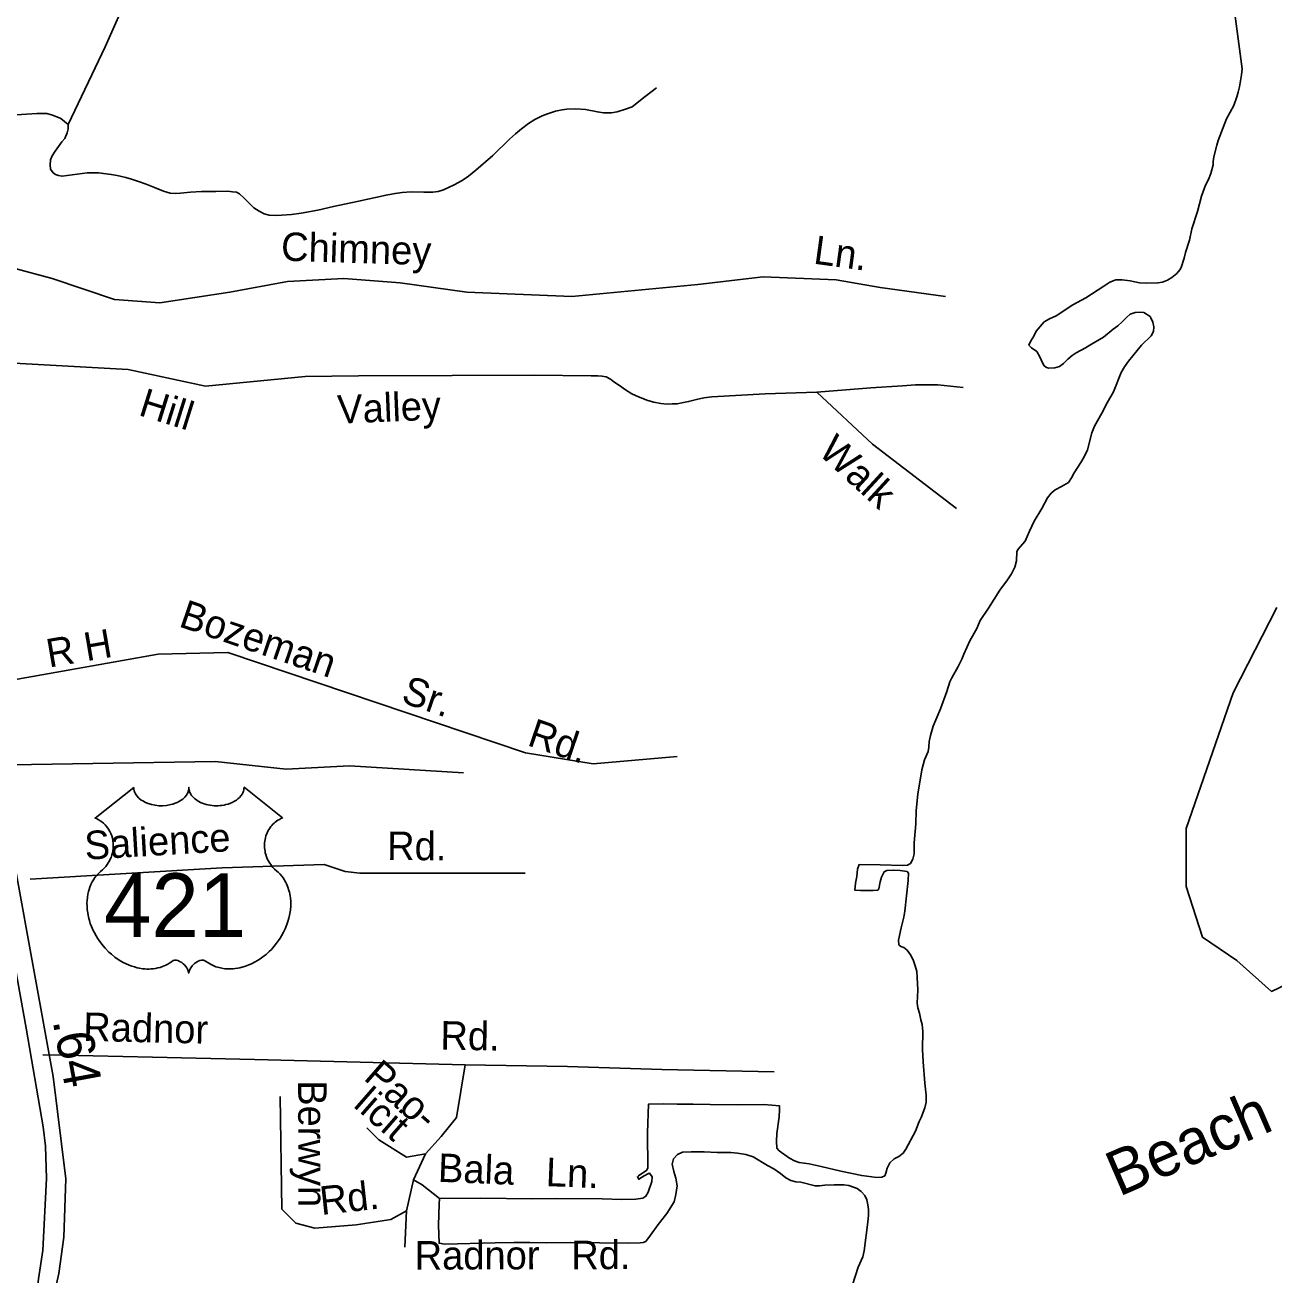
# Model space of a CAD drawing. Extents: x 2290055 to 2389491, y 66597 to 237875.
# Drawn here: x 2334742 to 2338909, y 120949 to 125120 of the extents above; entities that cross this region are included whole.
import ezdxf

# ---------------------------------------------------------------- set-up
doc = ezdxf.new("R2010")
doc.units = 0
for name, color, linetype in [('Exist Hydrographic Island Shore', 7, 'Continuous'), ('Exist Hydrographic Point Label', 7, 'Continuous'), ('Exist Hydrographic River Shore', 7, 'Continuous'), ('Exist Road Non-System Type 51', 7, 'Continuous'), ('Exist Road Non-System Type 51 Label', 7, 'Continuous'), ('Exist Road Primary US Divided Attributed', 7, 'Continuous'), ('Exist Road Primary US Mileage Hundredths English Label', 7, 'Continuous'), ('Exist Road Primary US Shield CELL', 7, 'Continuous'), ('Exist Road Primary US Shield Number Label', 7, 'Continuous')]:
    doc.layers.add(name, color=color, linetype=linetype)

msp = doc.modelspace()

# ---------------------------------------------------------------- linework, layer by layer
at = {"layer": 'Exist Hydrographic Island Shore'}
for points in [[(2338100.5, 124042.7), (2338117.7, 124030.4), (2338128.2, 124012.3), (2338136.7, 123992.2), (2338142.5, 123983.2), (2338150.5, 123977), (2338158.2, 123974.5), (2338178, 123975.7), (2338193, 123980.4), (2338206.5, 123991), (2338220.7, 124004.7), (2338235.5, 124017.6), (2338248.7, 124026.3), (2338280.5, 124042.5), (2338300.7, 124055.4), (2338339.7, 124078.3), (2338372.7, 124105.4), (2338388.5, 124116.3), (2338403, 124129.1), (2338417, 124144), (2338429, 124155.4), (2338445.7, 124161), (2338461, 124162), (2338474.7, 124160.5), (2338496, 124146.8), (2338498.5, 124142.9), (2338505, 124128.1), (2338508.5, 124113.1), (2338506.7, 124097.8), (2338499.5, 124082.9), (2338467, 124051.6), (2338423.2, 123998.3), (2338410, 123979.3), (2338399.5, 123960.6), (2338373.2, 123896.1), (2338352, 123859.1), (2338334.2, 123824.8), (2338310.5, 123781.6), (2338301.5, 123759.5), (2338286.5, 123702.6), (2338275.2, 123678.7), (2338265, 123660.5), (2338242.5, 123625.7), (2338233.5, 123608.8), (2338223.7, 123593.7), (2338200, 123579.8), (2338179, 123569.4), (2338165.5, 123557.7), (2338153, 123542.4), (2338134, 123507), (2338108.7, 123464.2), (2338093, 123430.8), (2338086, 123413), (2338078.5, 123398.1), (2338054, 123370.2), (2338050.5, 123362.1), (2338049.7, 123332.3), (2338044.2, 123311.3), (2338033, 123288.5), (2338019.5, 123268.5), (2337994.2, 123234.2), (2337956.2, 123173.6), (2337929.2, 123133.3), (2337917, 123106.3), (2337894.5, 123064.6), (2337874.2, 123020), (2337868, 123003.8), (2337855.7, 122979.9), (2337834, 122942), (2337828, 122928.2), (2337817, 122895.5), (2337796.2, 122838.6), (2337772, 122780.3), (2337762.7, 122749), (2337759, 122728.7), (2337757.2, 122709.9), (2337755, 122695.9), (2337742.5, 122668), (2337734, 122634.5), (2337720.2, 122553.1), (2337715.5, 122498.6), (2337714, 122454.7), (2337708.2, 122391.5), (2337708.2, 122354.1), (2337704, 122336.4), (2337696.2, 122321.6), (2337686.7, 122316.4), (2337669.5, 122315.5), (2337594.7, 122318), (2337524.5, 122318.3), (2337519.5, 122303.3), (2337517, 122278.4), (2337512.7, 122256.6), (2337510.7, 122232.9), (2337529.5, 122231.7), (2337571.2, 122232.1), (2337587.2, 122233.1), (2337590, 122237.5), (2337594.5, 122260.5)], [(2338918.3, 123175.9), (2338773.3, 122892), (2338616.2, 122438.9), (2338616.2, 122245.6), (2338670.6, 122076.4), (2338785.4, 121997.9), (2338900.2, 121895.2), (2339002.9, 121943.5)], [(2337594.5, 122260.5), (2337599, 122276.5), (2337608, 122294.4), (2337617.7, 122298.6), (2337638.5, 122299.5), (2337661.7, 122299.2), (2337685, 122295.5), (2337689.5, 122289.9), (2337688.5, 122265.7), (2337677.5, 122163), (2337673.5, 122142.7), (2337664.7, 122107.5), (2337656.7, 122066.1), (2337657.7, 122050.7), (2337663.7, 122045.5), (2337673.5, 122042), (2337685.2, 122032.5), (2337696.5, 122017.8), (2337705, 122000.4), (2337711.7, 121980.8), (2337717, 121961.2), (2337719, 121941.8), (2337720.2, 121900.5), (2337718.2, 121855.7), (2337720.2, 121840), (2337726.2, 121822.1), (2337731, 121800.2), (2337735.5, 121784.9), (2337737.7, 121762), (2337736.2, 121701), (2337738.5, 121660.6), (2337744, 121589), (2337749, 121548.7), (2337749, 121525.4), (2337744.2, 121506.4), (2337731.7, 121475), (2337725, 121460.7), (2337712.7, 121428.6), (2337681, 121369.2), (2337672, 121355.9), (2337657.7, 121344.2), (2337641.5, 121336.7), (2337627.7, 121323.4), (2337618, 121305.7), (2337613.7, 121288.6), (2337610.2, 121280.2), (2337601, 121275.1), (2337583.5, 121274.3), (2337533.5, 121280.4), (2337464.2, 121295.2), (2337398, 121311.5), (2337358, 121319.6), (2337325.2, 121324.2), (2337309.2, 121329.4), (2337292.2, 121339.3)], [(2337292.2, 121339.3), (2337258.5, 121363), (2337250, 121372.5), (2337248.7, 121395.9), (2337250.5, 121421.5), (2337257.5, 121477.2), (2337259.5, 121500), (2337259.2, 121513.1), (2337233.5, 121515.8), (2337206, 121517.3), (2337120.5, 121516.8), (2337027.7, 121517.5), (2336971.5, 121519.1), (2336918, 121519), (2336871, 121519.9), (2336822.2, 121519.5), (2336819.2, 121423.7), (2336820.2, 121306.4), (2336816.7, 121298.9), (2336789, 121280.2), (2336785.2, 121276.7), (2336789.5, 121268.5), (2336807.5, 121279.7), (2336821.7, 121287.5), (2336825.5, 121288.3), (2336834.5, 121276), (2336833, 121260.5), (2336820.5, 121225.8), (2336813.5, 121211.5), (2336803.5, 121205.4), (2336780, 121201.6), (2336733, 121200.8), (2336667.7, 121203), (2336515, 121204), (2336434.5, 121203), (2336260, 121205.2), (2336125, 121204.3), (2336123, 121185.6), (2336121.5, 121115.5), (2336123.2, 121055), (2336142, 121052.1), (2336310.5, 121056.4), (2336373.2, 121057), (2336426.5, 121057.2), (2336480.5, 121056), (2336561.7, 121056.8), (2336755.7, 121055.6), (2336794.5, 121056.5), (2336804.5, 121057.4), (2336812.7, 121061.2), (2336829, 121081.8), (2336854, 121117.4), (2336883.2, 121153.8), (2336907.2, 121193.5), (2336913.7, 121218), (2336917.7, 121246.2), (2336913.5, 121272), (2336907, 121294.4), (2336901.2, 121318.6), (2336905, 121336.2), (2336918.5, 121351), (2336935, 121358.3), (2336964, 121359.5), (2337008, 121359.6), (2337051.2, 121357.7), (2337097, 121357.3), (2337119.5, 121355.7), (2337146.5, 121351.2), (2337171, 121343.2), (2337218.7, 121314.4), (2337240, 121302.9), (2337262.2, 121287.3), (2337280.5, 121272.8), (2337297, 121263.9), (2337313.7, 121259.7), (2337330, 121258.5), (2337377.7, 121246.1), (2337392.7, 121246.2), (2337410.7, 121249), (2337441.5, 121250.3), (2337474.2, 121249.4), (2337490.5, 121247.1), (2337518, 121237), (2337532, 121227.4), (2337544, 121213.8), (2337550.2, 121199.5), (2337554.2, 121183.3), (2337555.7, 121168), (2337555.7, 121148.3), (2337554.2, 121124.8), (2337541.5, 121029.3), (2337537, 121009.7), (2337522, 120975.2), (2337503.2, 120915.8)]]:
    msp.add_lwpolyline(points, dxfattribs=at)
at = {"layer": 'Exist Hydrographic River Shore'}
msp.add_lwpolyline([(2338730.7, 125517.8), (2338802.7, 124973.8), (2338800.5, 124953.4), (2338793.7, 124913.8), (2338790, 124895.7), (2338785.5, 124879.9), (2338774.7, 124851.4), (2338750.7, 124807.3), (2338722.7, 124734.7), (2338718, 124719.3), (2338708.7, 124680.1), (2338706.2, 124665), (2338706.2, 124653.7), (2338698.5, 124624.1), (2338690.2, 124604.2), (2338680.7, 124585.3), (2338667.5, 124548.9), (2338653.7, 124497.5), (2338635.2, 124439.4), (2338626.7, 124401.9), (2338614, 124360.5), (2338609.5, 124342.1), (2338599, 124310.8), (2338594.5, 124302.6), (2338584.5, 124290.3), (2338568.7, 124277.3), (2338553.5, 124268.8), (2338536.5, 124261.9), (2338521.7, 124259.2), (2338482.7, 124258.3), (2338460.2, 124260), (2338428.7, 124266.3), (2338402.5, 124269.6), (2338381.5, 124269.7), (2338361.7, 124261.4), (2338341, 124249), (2338281.2, 124210.1), (2338237.5, 124186), (2338182, 124149.8), (2338159.5, 124139.1), (2338142, 124129.3), (2338116, 124098), (2338107.5, 124081.9), (2338096.5, 124064), (2338091.2, 124051.3), (2338100.5, 124042.7)], dxfattribs=at)
at = {"layer": 'Exist Road Non-System Type 51'}
for p, q in [((2334646.5, 122924.3), (2335186.4, 123020.5)), ((2334800.9, 121684.1), (2334870, 121682.5))]:
    msp.add_line(p, q, dxfattribs=at)
for points in [[(2334885.5, 124788.2), (2335008.9, 125047.1), (2335095.1, 125240.2), (2335102.8, 125260.2), (2335104.8, 125270.1), (2335105.3, 125281.6), (2335101.5, 125293.6), (2335094.3, 125302.2), (2335086.2, 125307.8), (2335072.9, 125312.2), (2335064.4, 125311.8), (2334780, 125322.9), (2334218.9, 125326.6)], [(2334885.5, 124788.2), (2334885.8, 124782), (2334886.1, 124773.8), (2334882, 124759.8), (2334874.2, 124741.8), (2334864.2, 124729.6), (2334842.7, 124699.2), (2334832.5, 124683.4), (2334826.5, 124670), (2334825.2, 124653.9), (2334827.1, 124639.2), (2334835.4, 124627), (2334843.2, 124621.4), (2334853.8, 124617.6), (2334865.4, 124615.4), (2334949.3, 124626.6), (2334971.3, 124626.8), (2334987.4, 124626.8), (2335029.3, 124621.2), (2335049.5, 124617.4), (2335077.6, 124611.6), (2335097.5, 124605.9), (2335119.8, 124598.2), (2335145.8, 124588.4), (2335173.5, 124577.3), (2335204.1, 124565.1), (2335226, 124559.1), (2335244.2, 124557.5), (2335260.2, 124559.4), (2335294.2, 124561.8), (2335330.2, 124564.2), (2335378.1, 124564.8), (2335418.1, 124565), (2335434, 124563.3), (2335446.8, 124562.2), (2335457.2, 124557), (2335474.2, 124541.6), (2335490.3, 124523.9), (2335504.7, 124510), (2335522.9, 124498.3), (2335539.6, 124490.1), (2335555.9, 124485.5), (2335576.9, 124484.6), (2335598.9, 124485.2), (2335630.9, 124487.4), (2335662.9, 124491.7), (2335718.6, 124502.1), (2335770.6, 124514.9), (2335850.4, 124531.5), (2335946.4, 124552.7), (2335976.7, 124557.9), (2336000.2, 124561.1), (2336030.3, 124562.9), (2336072.1, 124562), (2336102.3, 124562.2), (2336120.2, 124564.5), (2336138, 124570.5), (2336154.5, 124577.7), (2336174.1, 124587), (2336200.2, 124600.8), (2336221.6, 124615.5), (2336245.4, 124635.8), (2336302.9, 124684.3), (2336358.5, 124739), (2336378.1, 124757.2), (2336398.2, 124773.4), (2336421.7, 124791.4), (2336442.9, 124804.4), (2336466.7, 124816.5), (2336485.4, 124824.1), (2336511.4, 124832.4), (2336533.5, 124836.9), (2336549.5, 124838.8), (2336579.7, 124840), (2336611.6, 124837.6), (2336651.6, 124830), (2336671.4, 124826.9), (2336698.3, 124826.9), (2336717.5, 124830.7), (2336745.4, 124839), (2336767.4, 124847.1), (2336811, 124881.6), (2336848.7, 124910)], [(2334311.1, 124795.1), (2334679.2, 124817.8), (2334781.3, 124824.8), (2334799.4, 124825.1), (2334814.2, 124824.4), (2334833.4, 124819.3), (2334847.4, 124813.9), (2334861.4, 124807.6), (2334885.5, 124788.2)], [(2334318.4, 124280.4), (2334639.2, 124315.1), (2334700.1, 124310), (2334831.9, 124274.5), (2335039.8, 124203.5), (2335191.9, 124193.3), (2335425.1, 124228.8), (2335617.7, 124264.4), (2335805.3, 124274.5), (2335992.9, 124259.3), (2336216, 124228.8), (2336565.8, 124213.6), (2336986.6, 124254.2), (2337204.6, 124279.6), (2337448, 124269.4), (2337595, 124244.1)], [(2337595, 124244.1), (2337813, 124213.6)], [(2335676.2, 123947.5), (2335344, 123914.3), (2335085.4, 123970.1), (2334404.6, 124008.1)], [(2335676.2, 123947.5), (2335854.7, 123949.5), (2336166.8, 123950.6), (2336440.5, 123951.6), (2336630.6, 123949.3), (2336652.9, 123949.8), (2336666.4, 123948.7), (2336680.9, 123946), (2336694.7, 123938), (2336706.9, 123929.6), (2336725.1, 123916.6), (2336745.3, 123902.6), (2336766.9, 123889.3), (2336788.9, 123878.7), (2336819.6, 123867.4), (2336839.8, 123861.7), (2336863, 123857), (2336884.1, 123854.9), (2336900.8, 123855.6), (2336917.8, 123856.2), (2336938.7, 123860), (2336955.6, 123863.6), (2336982.2, 123870.9), (2337006.4, 123875.5), (2337033.8, 123879.5), (2337211.6, 123889.5), (2337383.7, 123895.3)], [(2337383.7, 123895.3), (2337563.7, 123909), (2337669.4, 123916.1), (2337713.3, 123918.8), (2337787.4, 123919.5), (2337871.5, 123910.3)], [(2337849.7, 123506.1), (2337569.4, 123721.1), (2337383.7, 123895.3)], [(2335186.4, 123020.5), (2335418.1, 123026.6), (2336412.1, 122691), (2336637.7, 122654.3), (2336918.2, 122678.8)], [(2334626.5, 122650.3), (2335376.5, 122662.5), (2335613.2, 122636.5), (2335824, 122648.1), (2336205, 122625)], [(2334758.7, 122269.6), (2335399.6, 122307.2), (2335740.3, 122318.8), (2335809.5, 122295.6), (2335858.6, 122289.9), (2336410, 122289.9)], [(2334870, 121682.5), (2335167.6, 121675.7), (2335507.9, 121667.5), (2335860.1, 121658.8), (2336210, 121650.6), (2336552.3, 121644.1), (2336866.4, 121635.1), (2337241.2, 121627.3)], [(2336210, 121650.6), (2336181.9, 121474.6), (2336130, 121411.1), (2336078, 121353.3), (2336014.5, 121341.7), (2335922.1, 121399.5), (2335881.7, 121440)], [(2336014.5, 121162.6), (2335962.5, 121133.7), (2335847.1, 121116.4), (2335708.5, 121104.9), (2335645, 121122.2), (2335598.8, 121168.4), (2335593, 121544)], [(2336078, 121353.3), (2336037.6, 121266.6), (2336066.5, 121249.3), (2336125, 121204.3)], [(2336037.6, 121266.6), (2336014.5, 121162.6), (2336008.7, 121041.3)]]:
    msp.add_lwpolyline(points, dxfattribs=at)
at = {"layer": 'Exist Road Primary US Divided Attributed'}
for points in [[(2334523.5, 119587), (2334685.9, 120257.1), (2334799.5, 120712.5), (2334854.5, 120954.2), (2334871.5, 121075.2), (2334878, 121269.7), (2334835.2, 121611.3), (2334709.3, 122310), (2334646.5, 122661.5), (2334542.7, 123249.2), (2334508.9, 123436.4)], [(2334526.2, 122980.8), (2334562.7, 122810.4), (2334605.9, 122554.4), (2334663.8, 122225.2), (2334717.7, 121927.1), (2334745.2, 121772.4), (2334774.3, 121604.4), (2334802.2, 121443.6), (2334810.4, 121378.3), (2334813.2, 121270.8), (2334801.4, 121030.8), (2334787, 120936), (2334778.8, 120870.3), (2334741.5, 120705.8), (2334654.3, 120356.9), (2334522.3, 119830.8), (2334466.3, 119591.7)]]:
    msp.add_lwpolyline(points, dxfattribs=at)
at = {"layer": 'Exist Road Primary US Shield CELL'}
msp.add_lwpolyline([(2335104.3, 122576), (2335104.7, 122570.6), (2335106, 122564.3), (2335106.9, 122561.1), (2335109.9, 122554.8), (2335114.8, 122547.5), (2335121.6, 122540.2), (2335129.2, 122533.9), (2335134.4, 122530.6), (2335143.2, 122525.9), (2335153.1, 122521.7), (2335164.2, 122518.5), (2335175.5, 122516.2), (2335187.9, 122514.9), (2335200.1, 122514.6), (2335213.3, 122515.6), (2335227.9, 122518.4), (2335234.7, 122520.2), (2335242.2, 122522.8), (2335249.2, 122525.7), (2335256.9, 122529.8), (2335263, 122533.7), (2335267.8, 122537.2), (2335274.7, 122543.7), (2335280.1, 122550.5), (2335282.4, 122554.3), (2335284.4, 122558), (2335287.1, 122565.7), (2335287.8, 122569.1), (2335288.4, 122576.2), (2335288.8, 122570.3), (2335289.4, 122566.5), (2335290.4, 122562.9), (2335291.9, 122559), (2335294.6, 122553.5), (2335297.7, 122549), (2335303.4, 122542.2), (2335307, 122538.9), (2335310.3, 122536.2), (2335319, 122530.2), (2335329.2, 122525), (2335334.2, 122522.8), (2335339.4, 122521), (2335345.9, 122519), (2335352.7, 122517.5), (2335359.4, 122516.3), (2335366.2, 122515.3), (2335373.2, 122514.8), (2335378.9, 122514.6), (2335385.9, 122514.7), (2335392.3, 122515.1), (2335398.9, 122515.9), (2335406.2, 122517.1), (2335412.1, 122518.4), (2335419.8, 122520.4), (2335426.8, 122522.9), (2335432.9, 122525.6), (2335440.9, 122529.8), (2335447.4, 122533.8), (2335452.1, 122537.6), (2335457.7, 122542.8), (2335463, 122548.9), (2335466.1, 122553.4), (2335468.3, 122558), (2335470.4, 122562.9), (2335471.6, 122568.1), (2335472.3, 122572.5), (2335472.4, 122576.4), (2335601, 122473.9), (2335597.9, 122472.8), (2335591, 122469.4), (2335585.4, 122466.1), (2335576.6, 122459.9), (2335572.8, 122456.4), (2335569, 122452.9), (2335565.5, 122449.1), (2335562.4, 122445.5), (2335558.7, 122440.3), (2335555.3, 122435.2), (2335552.1, 122429.5), (2335549.7, 122424.5), (2335545.7, 122414.2), (2335543.8, 122407.6), (2335542.6, 122402.1), (2335541.1, 122390.6), (2335540.7, 122385.2), (2335540.7, 122379.8), (2335541, 122374.1), (2335541.6, 122368.6), (2335542.5, 122362.9), (2335543.4, 122357.9), (2335545, 122351.7), (2335547.3, 122344.6), (2335550.1, 122337.7), (2335556, 122326.5), (2335563.6, 122315.1), (2335569, 122308.7), (2335574.3, 122303.2), (2335582.2, 122296.6), (2335586.5, 122292.8), (2335591.4, 122287.8), (2335599.5, 122278.5), (2335602.8, 122274.1), (2335606.1, 122269.1), (2335609.1, 122264), (2335612.1, 122258.6), (2335614.6, 122253.8), (2335619.1, 122242.8), (2335622.4, 122232), (2335623.9, 122226.4), (2335626.3, 122213.8), (2335627.2, 122207.6), (2335628.2, 122195.3), (2335628.2, 122180.4), (2335627.1, 122166.2), (2335624.4, 122149.7), (2335622.2, 122139.9), (2335618.9, 122128.4), (2335615.6, 122118.4), (2335609.7, 122103.8), (2335604.5, 122093.1), (2335597.8, 122080.7), (2335593.1, 122073.2), (2335587.7, 122065.1), (2335581, 122055.8), (2335573.1, 122046), (2335563.6, 122035.5), (2335555.9, 122027.9), (2335545.9, 122018.9), (2335539.8, 122013.9), (2335531.1, 122007.3), (2335519.3, 121999.4), (2335507.6, 121992.7), (2335497.7, 121987.6), (2335488.8, 121983.8), (2335477.5, 121979.5), (2335458.5, 121974.2), (2335451.6, 121972.8), (2335443.4, 121971.6), (2335435.7, 121970.8), (2335428.2, 121970.3), (2335418.2, 121970.3), (2335408.3, 121971.1), (2335398.8, 121972.5), (2335389.1, 121974.5), (2335378.8, 121977.6), (2335369.5, 121981.2), (2335360.1, 121985.8), (2335344.2, 121995.9), (2335339.6, 121998.3), (2335337, 121999), (2335330.8, 121999.3), (2335325.1, 121998.1), (2335319.1, 121995.7), (2335315.6, 121993.8), (2335310.8, 121990.7), (2335307.2, 121987.8), (2335302.8, 121983.6), (2335299.7, 121980.1), (2335297.4, 121977.4), (2335292.9, 121970.3), (2335291.3, 121967), (2335289.7, 121962.7), (2335288.2, 121956.3), (2335286.2, 121964.3), (2335283.8, 121969.7), (2335281.1, 121974.2), (2335278.2, 121978.2), (2335273.8, 121983.4), (2335269.7, 121987.3), (2335264.9, 121991.2), (2335259.7, 121994.4), (2335255.6, 121996.5), (2335251.8, 121997.9), (2335247.1, 121999.1), (2335243.3, 121999.4), (2335240.2, 121999.3), (2335235.9, 121998.3), (2335230.1, 121994.1), (2335224.6, 121990.3), (2335218.6, 121986.6), (2335211.5, 121982.8), (2335206.2, 121980.4), (2335200, 121977.9), (2335192.7, 121975.5), (2335184.8, 121973.5), (2335176.7, 121971.9), (2335169.6, 121970.7), (2335161.9, 121970), (2335155, 121969.8), (2335147.8, 121969.9), (2335141, 121970.4), (2335133.2, 121971.1), (2335123.5, 121972.5), (2335115.4, 121974.4), (2335106.9, 121976.7), (2335098.2, 121979.4), (2335088.8, 121983), (2335077.1, 121988), (2335069, 121992.2), (2335056.2, 121999.6), (2335041.1, 122010), (2335029.8, 122019.2), (2335021.5, 122026.7), (2335009.2, 122039.2), (2335002.1, 122047.3), (2334990.8, 122061.9), (2334983.6, 122072.5), (2334978.9, 122080.2), (2334972.1, 122092.7), (2334968.3, 122100.5), (2334963.4, 122111.9), (2334959.6, 122122.3), (2334956.4, 122132.2), (2334954.7, 122138.5), (2334952.3, 122149.5), (2334950.8, 122157.3), (2334949.4, 122168.1), (2334948.6, 122179.4), (2334948.4, 122189.8), (2334948.7, 122198.5), (2334949.7, 122208.6), (2334951.4, 122219.3), (2334953.4, 122228.5), (2334955.3, 122235.1), (2334958, 122243.1), (2334961.6, 122252), (2334965.9, 122260.5), (2334969.9, 122267.6), (2334975, 122275.2), (2334980, 122281.7), (2334986.6, 122288.8), (2334993.4, 122295.3), (2334999.7, 122300.4), (2335007.2, 122307.7), (2335011, 122312.1), (2335015.7, 122318.3), (2335019.4, 122324), (2335022.4, 122329.1), (2335026.3, 122336.6), (2335028.7, 122342.2), (2335031.6, 122350.9), (2335033.1, 122357), (2335034.6, 122364.8), (2335035.6, 122372.2), (2335036, 122381.4), (2335035.8, 122389), (2335034.8, 122397.8), (2335033.1, 122406.4), (2335031.1, 122413.8), (2335027.9, 122422.3), (2335025, 122428.5), (2335020, 122437), (2335014.6, 122444.8), (2335008.9, 122451.2), (2335003.2, 122456.9), (2334997.7, 122461.1), (2334992.5, 122464.9), (2334986, 122468.8), (2334979.7, 122471.9), (2334975.7, 122473.5)], close=True, dxfattribs=at)

# ---------------------------------------------------------------- texts
at = {"layer": 'Exist Hydrographic Point Label'}
msp.add_text('Beach', height=150, rotation=23.3556, dxfattribs=at).set_placement((2338391.5, 121209))
at = {"layer": 'Exist Road Non-System Type 51 Label'}
for s, rotation, p in [('Chimney', 358.2239, (2335595, 124333.8)), ('Ln.', 352.1611, (2337369.8, 124324.1)), ('Hill ', 342.5455, (2335116.8, 123819.2)), ('Valley', 2.3896, (2335785.5, 123789.5)), ('Walk', 317.3625, (2337384.8, 123690.7)), ('Bozeman       Sr.        Rd.', 341.1701, (2335251.1, 123114)), ('R H', 9.6624, (2334821.7, 122975.6)), ('Salience', 3.3678, (2334943, 122334.6)), ('Rd.', 359.5839, (2335949.6, 122333.9)), ('Radnor', 358.6945, (2334935.1, 121730.2)), ('Rd.', 358.911, (2336126.9, 121701.4)), ('Pao-', 318.8822, (2335868.1, 121603.1)), ('Berwyn', 270.1448, (2335652.9, 121598.7)), ('licit', 318.8822, (2335833.7, 121512)), ('Bala   Ln.', 357.7295, (2336118.3, 121260)), ('Rd.', 6.2918, (2335730.5, 121149.1)), ('Radnor   Rd.', 0.1276, (2336041.8, 120967))]:
    msp.add_text(s, height=95, rotation=rotation, dxfattribs=at).set_placement(p)
at = {"layer": 'Exist Road Primary US Mileage Hundredths English Label'}
msp.add_text('.64', height=125, rotation=280.4949, dxfattribs=at).set_placement((2334833.6, 121796.6))
at = {"layer": 'Exist Road Primary US Shield Number Label'}
msp.add_text('421', height=212.5, dxfattribs=at).set_placement((2335005.5, 122076.7))

doc.saveas('drawing.dxf')
